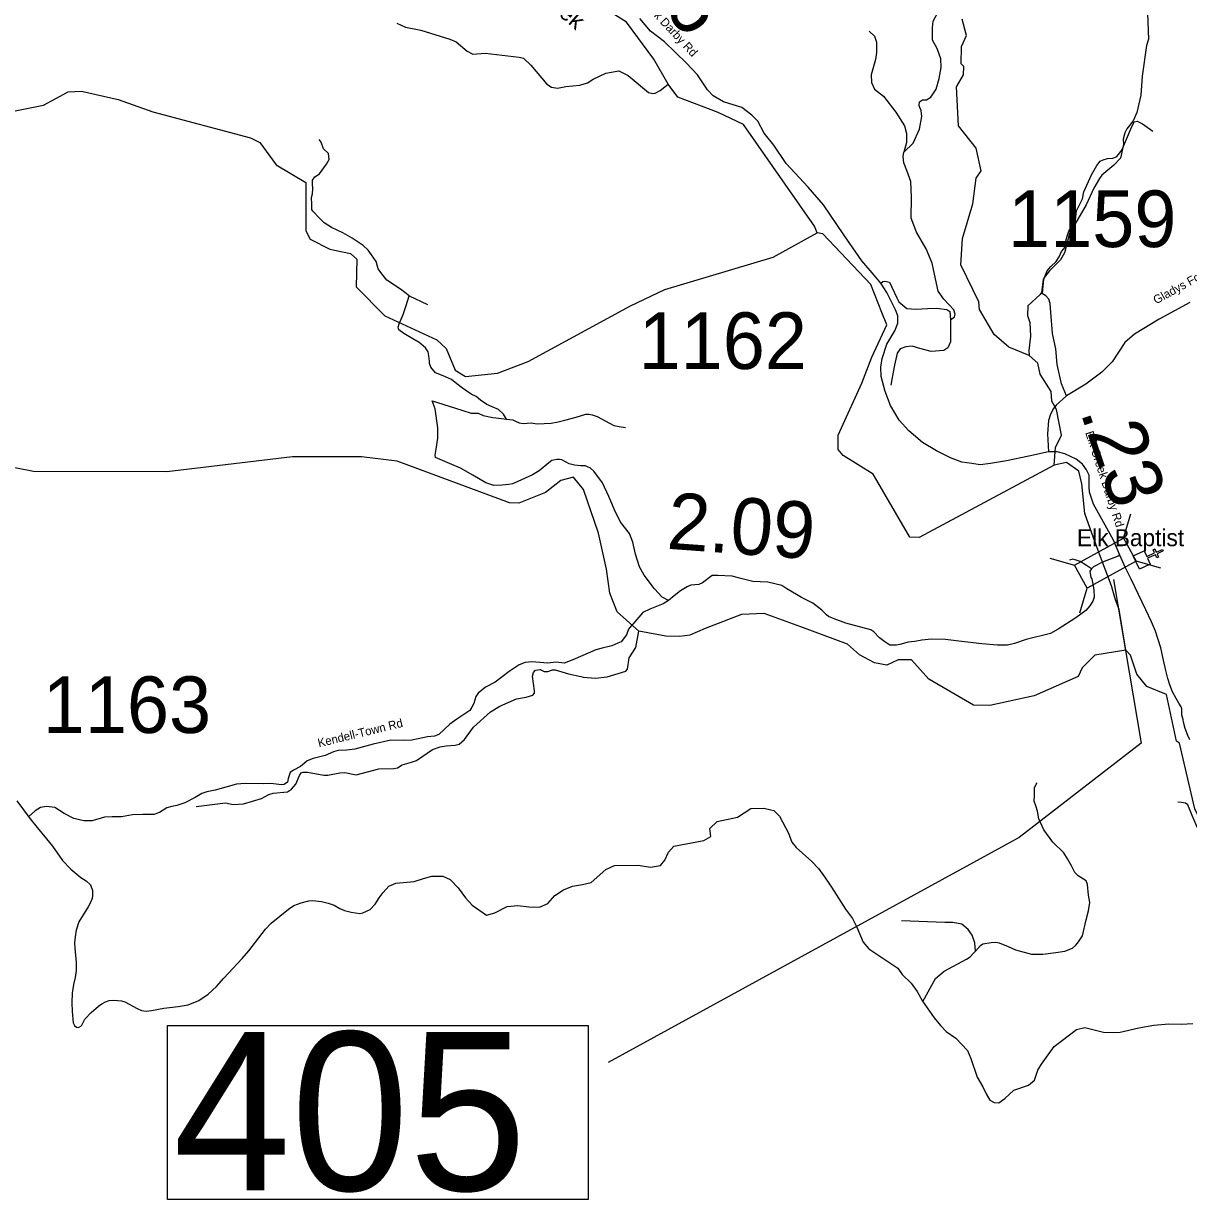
# Model space of a CAD drawing. Extents: x 1248224 to 1454986, y 825081 to 985870.
# Drawn here: x 1277074 to 1287366, y 852532 to 862920 of the extents above; entities that cross this region are included whole.
import ezdxf

# ---------------------------------------------------------------- set-up
doc = ezdxf.new("R2010")
doc.units = 0
for name, color, linetype in [('Exist Boundary Political CountyLine', 7, 'Continuous'), ('Exist Cultural Church CELL', 7, 'Continuous'), ('Exist Cultural Church Label', 7, 'Continuous'), ('Exist Hydrographic Creek Single Shore', 7, 'Continuous'), ('Exist Hydrographic Creek Single Shore Label', 7, 'Continuous'), ('Exist Hydrographic Misc Water Feature', 7, 'Continuous'), ('Exist Road Non-System Type 51', 7, 'Continuous'), ('Exist Road Secondary Mileage Hundredths English Label', 7, 'Continuous'), ('Exist Road Secondary Structure Standard Bridge CELL', 7, 'Continuous'), ('Exist Road Secondary Structure Standard Bridge Number Label', 7, 'Continuous'), ('Exist Road Secondary Type 41 Attributed', 7, 'Continuous'), ('Exist Road Secondary Type 51 Attributed', 7, 'Continuous'), ('Exist Road Secondary Type 51 Label', 7, 'Continuous'), ('Exist Road Secondary Type 51 Number Label', 7, 'Continuous')]:
    doc.layers.add(name, color=color, linetype=linetype)

msp = doc.modelspace()

# ---------------------------------------------------------------- linework, layer by layer
at = {"layer": 'Exist Boundary Political CountyLine'}
for points in [[(1277016, 856053), (1277134, 855896), (1277194, 855817), (1277277, 855718), (1277331, 855652), (1277418, 855527), (1277491, 855449), (1277580, 855377), (1277627, 855347), (1277665, 855312), (1277684, 855262), (1277685, 855217), (1277682, 855191), (1277666, 855155), (1277644, 855117), (1277564, 854986), (1277539, 854912), (1277529, 854853), (1277525, 854798), (1277527, 854753), (1277540, 854626), (1277539, 854556), (1277529, 854493), (1277515, 854430), (1277504, 854355), (1277500, 854268), (1277503, 854194), (1277514, 854093), (1277525, 854069), (1277541, 854054), (1277560, 854052), (1277581, 854063), (1277590, 854073), (1277616, 854124), (1277671, 854183), (1277736, 854240), (1277767, 854262), (1277798, 854279), (1277831, 854289)], [(1277831, 854289), (1277870, 854292), (1277940, 854288), (1277968, 854278), (1278079, 854218), (1278117, 854203), (1278157, 854197), (1278206, 854202), (1278315, 854223), (1278441, 854236), (1278528, 854252), (1278624, 854290), (1278704, 854346), (1278779, 854415), (1278845, 854486), (1279005, 854660), (1279065, 854729), (1279212, 854919), (1279263, 854972), (1279416, 855097), (1279463, 855128), (1279527, 855154), (1279595, 855170), (1279631, 855173), (1279706, 855164), (1279765, 855150), (1279819, 855132), (1279869, 855103), (1279909, 855085), (1279968, 855069), (1280044, 855058), (1280072, 855065), (1280136, 855093), (1280181, 855142), (1280217, 855198), (1280251, 855244), (1280302, 855299), (1280364, 855326), (1280526, 855341), (1280609, 855368), (1280681, 855388), (1280778, 855388), (1280842, 855359), (1280914, 855285), (1280978, 855198), (1281037, 855132), (1281163, 855045), (1281237, 855063), (1281347, 855121), (1281441, 855128), (1281537, 855117), (1281633, 855113), (1281705, 855147), (1281767, 855217), (1281846, 855268), (1281924, 855300), (1282013, 855315), (1282088, 855332), (1282219, 855447), (1282295, 855483), (1282505, 855486), (1282612, 855467), (1282702, 855483), (1282739, 855529), (1282771, 855599), (1282818, 855652), (1283084, 855703), (1283145, 855740), (1283137, 855809), (1283202, 855871), (1283383, 855908), (1283501, 855985), (1283614, 855988), (1283675, 855973), (1283702, 855967), (1283753, 855919), (1283831, 855769), (1283863, 855689), (1283899, 855641), (1284039, 855519), (1284096, 855455), (1284151, 855383), (1284196, 855317), (1284213, 855291), (1284335, 855096), (1284398, 855015), (1284436, 854938), (1284491, 854804), (1284542, 854745), (1284797, 854577), (1284837, 854521), (1284917, 854444), (1284970, 854369), (1285015, 854285), (1285119, 854136), (1285174, 854069), (1285226, 854017), (1285312, 853956), (1285414, 853848), (1285444, 853779), (1285500, 853613)], [(1285500, 853613), (1285550, 853527), (1285580, 853465), (1285612, 853410), (1285648, 853388), (1285691, 853386), (1285743, 853424), (1285823, 853497), (1285953, 853542), (1286005, 853585), (1286035, 853674), (1286067, 853727), (1286180, 853884), (1286378, 854034), (1286449, 854052), (1286615, 854011), (1286700, 854008), (1286762, 854011), (1286928, 854048), (1287059, 854072), (1287191, 854085), (1287303, 854082), (1287404, 854086)]]:
    msp.add_lwpolyline(points, dxfattribs=at)
at = {"layer": 'Exist Cultural Church CELL'}
msp.add_lwpolyline([(1286974, 858262), (1286998, 858211), (1287067, 858243), (1287053, 858272), (1287068, 858279), (1287081, 858250), (1287136, 858275), (1287143, 858261), (1287088, 858235), (1287102, 858206), (1287087, 858199), (1287074, 858228), (1287005, 858196), (1287029, 858144), (1286932, 858099), (1286877, 858217)], close=True, dxfattribs=at)
at = {"layer": 'Exist Hydrographic Creek Single Shore'}
for points in [[(1284086, 861070), (1284062, 861130), (1283435, 862028), (1283211, 862135), (1282856, 862270), (1282770, 862384), (1282642, 862606), (1282401, 862931), (1281748, 863346), (1281569, 863517), (1280995, 864349), (1280777, 864531), (1280688, 864664), (1280667, 864870), (1280635, 865080), (1280391, 865474), (1280334, 865752), (1280154, 866011), (1280001, 866217), (1279969, 866258)], [(1286179, 859019), (1286191, 859176), (1286243, 859284), (1286199, 859511), (1286159, 859584), (1286153, 859670), (1286057, 859823), (1286034, 859921), (1285959, 859986), (1285779, 860061), (1285648, 860172), (1285520, 860395), (1285513, 860460), (1285355, 860789), (1285369, 861021), (1285460, 861328), (1285490, 861554), (1285534, 861619), (1285489, 861820), (1285335, 862017), (1285318, 862359), (1285379, 862466), (1285381, 862541), (1285357, 862565), (1285360, 862716), (1285404, 862813), (1285366, 862958)], [(1276957, 862139), (1277251, 862199), (1277470, 862316), (1277587, 862323), (1277911, 862248), (1278216, 862140), (1279078, 861909), (1279161, 861868), (1279306, 861672), (1279569, 861515), (1279567, 861089), (1279606, 861016), (1279780, 860927), (1279962, 860887), (1280019, 860837), (1280013, 860594), (1280265, 860339), (1280727, 860126), (1280809, 860049), (1280887, 859857), (1280978, 859803), (1281262, 859830), (1281531, 859933), (1282436, 860427), (1282739, 860569), (1283697, 860855), (1284086, 861070)], [(1286179, 859019), (1284987, 858380), (1284904, 858382), (1284580, 858939), (1284315, 859103), (1284271, 859157), (1284271, 859285), (1284479, 859743), (1284568, 859974), (1284701, 860257), (1284657, 860368), (1284560, 860613), (1284136, 861063), (1284086, 861070)], [(1282509, 857552), (1282319, 857723), (1282253, 857889), (1282224, 858099), (1282153, 858417), (1282020, 858804), (1281932, 858914), (1281822, 858883), (1281686, 858778), (1281451, 858684), (1281367, 858686), (1280375, 859053), (1280060, 859093), (1279451, 859092), (1278339, 858960), (1277163, 858964), (1276814, 859030), (1276621, 859303), (1276482, 859430), (1275897, 859705)], [(1286607, 858162), (1286527, 858377), (1286450, 858593), (1286423, 858855), (1286396, 858966), (1286288, 859043), (1286179, 859019)], [(1286685, 857954), (1286607, 858162)], [(1286814, 857385), (1286755, 857744), (1286721, 857828), (1286685, 857954)], [(1286814, 857385), (1286538, 857341), (1286426, 857228), (1286391, 857153), (1286003, 856981), (1285610, 856897), (1285468, 856900), (1285073, 857127), (1284919, 857298), (1284802, 857300), (1284701, 857253), (1284593, 857272), (1284461, 857343), (1284355, 857437), (1283942, 857590), (1283616, 857707), (1283417, 857700), (1283095, 857577), (1282961, 857516), (1282872, 857506), (1282749, 857509), (1282509, 857552)], [(1290064, 852793), (1290015, 852887), (1289863, 853130), (1289742, 853367), (1289499, 853667), (1289302, 854114), (1289141, 854686), (1288925, 855064), (1288789, 855213), (1288652, 855179), (1288449, 855034), (1288244, 854838), (1288177, 854807), (1288102, 854818), (1287963, 854946), (1287810, 855175), (1287422, 855984), (1287286, 856564), (1287261, 856581), (1287171, 856993), (1286998, 857063), (1286909, 857173), (1286855, 857341), (1286814, 857385)]]:
    msp.add_lwpolyline(points, dxfattribs=at)
at = {"layer": 'Exist Hydrographic Misc Water Feature'}
for points in [[(1287005, 863009), (1287014, 862780), (1286996, 862725), (1286956, 862454), (1286944, 862286), (1286910, 862135), (1286876, 862059), (1286822, 861990), (1286805, 861955), (1286790, 861899), (1286793, 861852), (1286766, 861731), (1286708, 861669), (1286600, 861580), (1286579, 861552), (1286529, 861464), (1286463, 861317), (1286315, 861064), (1286271, 860894), (1286234, 860832), (1286137, 860735), (1286092, 860676), (1286083, 860660), (1286068, 860544), (1286056, 860525), (1285947, 860425), (1285945, 860341), (1285964, 860280), (1285971, 860159), (1285956, 860031), (1285959, 859986)], [(1280373, 862922), (1280448, 862887), (1280583, 862860), (1280840, 862780), (1280895, 862757), (1280993, 862674), (1281044, 862649), (1281153, 862658), (1281452, 862623), (1281492, 862614), (1281556, 862552), (1281696, 862385), (1281740, 862358), (1281792, 862348), (1281864, 862362), (1281988, 862376), (1282057, 862395), (1282106, 862427), (1282219, 862480), (1282334, 862503), (1282415, 862461), (1282597, 862311), (1282633, 862302), (1282653, 862305), (1282698, 862328), (1282770, 862384)], [(1278598, 856004), (1278859, 856036), (1278927, 856022), (1279019, 856028), (1279176, 856074), (1279241, 856109), (1279281, 856120), (1279406, 856133), (1279442, 856157), (1279479, 856201), (1279511, 856276), (1279528, 856300), (1279544, 856307), (1279584, 856306), (1279728, 856280), (1279764, 856280), (1279868, 856301), (1279912, 856304), (1280012, 856284), (1280213, 856335), (1280345, 856338), (1280377, 856345), (1280418, 856372), (1280503, 856394), (1280547, 856411), (1280686, 856507), (1280754, 856530), (1280807, 856540), (1280887, 856544), (1280923, 856555), (1280970, 856595), (1281049, 856705), (1281200, 856839), (1281283, 856889), (1281429, 856955), (1281514, 856969), (1281574, 856988), (1281587, 857004), (1281587, 857024), (1281572, 857156), (1281581, 857188), (1281597, 857207), (1281638, 857215), (1281673, 857196), (1281705, 857195), (1281746, 857210), (1281770, 857210), (1281889, 857174), (1281998, 857153), (1282018, 857145), (1282126, 857138), (1282230, 857150), (1282394, 857198), (1282410, 857217), (1282425, 857317), (1282483, 857408), (1282509, 857552)]]:
    msp.add_lwpolyline(points, dxfattribs=at)
at = {"layer": 'Exist Road Non-System Type 51'}
for points in [[(1284852, 861784), (1284935, 861864), (1284989, 861986), (1285011, 862097), (1285005, 862152), (1284992, 862177), (1284986, 862196), (1284989, 862228), (1285015, 862247), (1285053, 862247), (1285091, 862270), (1285136, 862340), (1285164, 862434), (1285180, 862530), (1285177, 862607), (1285145, 862699), (1285104, 862773), (1285104, 862881), (1285110, 862939), (1285199, 863105)], [(1284546, 862852), (1284593, 862807), (1284609, 862756), (1284609, 862664), (1284600, 862603), (1284562, 862466), (1284565, 862399), (1284593, 862341), (1284673, 862278), (1284782, 862137), (1284858, 862016), (1284874, 861949), (1284874, 861869), (1284852, 861784)], [(1286289, 859630), (1286244, 859738), (1286206, 859909), (1286193, 860045), (1286166, 860183), (1286149, 860370), (1286144, 860447), (1286132, 860485), (1286106, 860513), (1286077, 860531), (1286079, 860570), (1286087, 860663), (1286119, 860734), (1286151, 860772), (1286198, 860817), (1286224, 860859), (1286245, 860906), (1286266, 860929), (1286281, 860953), (1286283, 860997), (1286294, 861040), (1286309, 861085), (1286368, 861183), (1286376, 861266), (1286431, 861370), (1286442, 861432), (1286508, 861583), (1286555, 861666), (1286587, 861704), (1286612, 861717), (1286650, 861726), (1286699, 861730), (1286729, 861743), (1286748, 861762), (1286778, 861800), (1286861, 861996), (1286886, 862050), (1286912, 862056), (1286961, 862033), (1287050, 861969)], [(1280481, 860513), (1280404, 860574), (1280284, 860653), (1280241, 860709), (1280208, 860752), (1280190, 860817), (1280149, 860875), (1280118, 860919), (1280074, 860960), (1279977, 861025), (1279895, 861071), (1279796, 861117), (1279730, 861158), (1279691, 861198), (1279629, 861262), (1279621, 861277), (1279621, 861324), (1279619, 861382), (1279627, 861416), (1279629, 861459), (1279626, 861503), (1279626, 861536), (1279649, 861566), (1279690, 861592), (1279751, 861678), (1279774, 861720), (1279769, 861771), (1279724, 861814), (1279705, 861873), (1279685, 861895)], [(1285263, 860302), (1285299, 860328), (1285305, 860353), (1285292, 860391), (1285206, 860484), (1285155, 860557), (1285123, 860707), (1285101, 860803), (1285050, 860928), (1284964, 861078), (1284916, 861199), (1284919, 861385), (1284913, 861523), (1284877, 861622), (1284852, 861689), (1284846, 861746), (1284852, 861784)], [(1284647, 860626), (1284667, 860640), (1284683, 860644), (1284724, 860634), (1284744, 860592), (1284788, 860497), (1284807, 860462), (1284878, 860401), (1284960, 860398), (1285059, 860401), (1285139, 860404), (1285232, 860395), (1285257, 860375), (1285263, 860302)], [(1281342, 859426), (1281315, 859470), (1281270, 859510), (1281214, 859534), (1281168, 859554), (1281111, 859592), (1281073, 859626), (1281029, 859646), (1280991, 859671), (1280953, 859699), (1280902, 859738), (1280855, 859776), (1280782, 859807), (1280715, 859835), (1280673, 859885), (1280660, 859918), (1280661, 859938), (1280656, 859984), (1280648, 860020), (1280625, 860054), (1280569, 860102), (1280515, 860135), (1280435, 860183), (1280390, 860214), (1280384, 860237), (1280394, 860268), (1280427, 860350), (1280456, 860429), (1280481, 860513)], [(1280481, 860513), (1280642, 860439)], [(1285263, 860302), (1285263, 860184), (1285263, 860107), (1285241, 860056), (1285206, 860031), (1285094, 860024), (1284992, 860050), (1284925, 860069), (1284868, 860063), (1284820, 860047), (1284791, 860008), (1284769, 859903), (1284747, 859794), (1284737, 859724)], [(1282773, 857823), (1282717, 857853), (1282650, 857927), (1282557, 858048), (1282515, 858120), (1282480, 858231), (1282456, 858337), (1282429, 858415), (1282350, 858512), (1282303, 858603), (1282244, 858741), (1282190, 858864), (1282113, 858965), (1282084, 858993), (1282056, 859004), (1282035, 859013), (1281994, 859013), (1281941, 859019), (1281895, 859031), (1281830, 859067), (1281808, 859070), (1281785, 859070), (1281743, 859059), (1281715, 859039), (1281631, 858970), (1281572, 858934), (1281442, 858875), (1281394, 858855), (1281363, 858848), (1281304, 858843), (1281230, 858840), (1281158, 858863), (1281044, 858930), (1280935, 858993), (1280837, 859034), (1280714, 859086), (1280711, 859106), (1280721, 859160), (1280734, 859257), (1280734, 859347), (1280712, 859517), (1280684, 859587)], [(1280684, 859587), (1280883, 859526), (1281028, 859479), (1281090, 859477), (1281134, 859457), (1281220, 859441), (1281298, 859431), (1281342, 859426)], [(1281342, 859426), (1281398, 859418), (1281421, 859408), (1281454, 859393), (1281489, 859387), (1281559, 859392), (1281613, 859385), (1281674, 859387), (1281736, 859390), (1281797, 859402), (1281856, 859415), (1281956, 859443), (1282043, 859469), (1282067, 859470), (1282097, 859462), (1282141, 859447), (1282212, 859410), (1282288, 859369), (1282335, 859360), (1282393, 859350)], [(1286509, 858102), (1286465, 858133), (1286410, 858167), (1286366, 858182), (1286344, 858187), (1286314, 858179)], [(1285483, 854725), (1285528, 854775), (1285550, 854790), (1285623, 854803), (1285665, 854805), (1285695, 854800), (1285773, 854768), (1285838, 854738), (1285980, 854700), (1286080, 854698), (1286193, 854713), (1286273, 854725), (1286340, 854753), (1286370, 854778), (1286395, 854808), (1286430, 854860), (1286463, 855003), (1286483, 855081), (1286495, 855156), (1286482, 855220), (1286475, 855315), (1286462, 855347), (1286392, 855390), (1286362, 855422), (1286332, 855480), (1286297, 855542), (1286265, 855593), (1286167, 855690), (1286087, 855798), (1286045, 855894), (1286032, 855962), (1286017, 856009), (1286002, 856052), (1286005, 856102), (1286005, 856169), (1286020, 856202), (1286030, 856212)], [(1287708, 855339), (1287668, 855364), (1287591, 855472), (1287566, 855527), (1287501, 855667), (1287496, 855697), (1287481, 855745), (1287466, 855777), (1287443, 855820), (1287398, 855925), (1287361, 856018), (1287341, 856033), (1287303, 856040), (1287273, 856043)], [(1285483, 854725), (1285480, 854800), (1285455, 854868), (1285420, 854918), (1285363, 854963), (1285283, 854980), (1285213, 854978), (1284830, 854993)], [(1285019, 854280), (1285130, 854483), (1285208, 854548), (1285405, 854655), (1285438, 854675), (1285468, 854708), (1285483, 854725)]]:
    msp.add_lwpolyline(points, dxfattribs=at)
at = {"layer": 'Exist Road Secondary Structure Standard Bridge CELL'}
for p, q in [((1286793, 858373), (1286856, 858590)), ((1286141, 858198), (1286358, 858135)), ((1286902, 858175), (1287120, 858112)), ((1286407, 857715), (1286470, 857932))]:
    msp.add_line(p, q, dxfattribs=at)
msp.add_lwpolyline([(1286358, 858135), (1286793, 858374), (1286904, 858171), (1286470, 857932)], close=True, dxfattribs=at)
at = {"layer": 'Exist Road Secondary Structure Standard Bridge Number Label'}
msp.add_lwpolyline([(1286704, 858010), (1286949, 856563), (1285870, 855729), (1282239, 853742)], dxfattribs=at)
msp.add_lwpolyline([(1278346, 854069), (1282062, 854069), (1282062, 852532), (1278346, 852532)], close=True, dxfattribs=at)
at = {"layer": 'Exist Road Secondary Type 41 Attributed'}
for points in [[(1284047, 857801), (1283947, 857849), (1283903, 857876), (1283819, 857927), (1283774, 857955), (1283650, 857986), (1283581, 857988), (1283516, 857992), (1283424, 858016), (1283335, 858037), (1283207, 858045), (1283159, 858043), (1283073, 857980), (1283039, 857966), (1282970, 857959), (1282937, 857943), (1282878, 857909), (1282821, 857864), (1282773, 857823), (1282724, 857795), (1282608, 857748), (1282545, 857717), (1282456, 857615), (1282442, 857598)], [(1282442, 857598), (1282420, 857570), (1282402, 857519), (1282355, 857458), (1282326, 857446), (1282272, 857422), (1282186, 857401), (1282131, 857387), (1282014, 857338), (1281928, 857298), (1281851, 857271), (1281780, 857279), (1281705, 857271), (1281565, 857281), (1281506, 857277), (1281452, 857256), (1281364, 857195), (1281242, 857102), (1281155, 857057), (1281090, 857006), (1281070, 856975), (1281053, 856912), (1281035, 856882), (1281017, 856851), (1280903, 856774), (1280841, 856732), (1280743, 856641), (1280705, 856624), (1280644, 856620), (1280560, 856600), (1280504, 856590), (1280441, 856588), (1280319, 856590), (1280164, 856555), (1280000, 856511), (1279929, 856502), (1279855, 856498), (1279813, 856486), (1279740, 856454), (1279691, 856443), (1279632, 856427), (1279581, 856407), (1279557, 856385), (1279520, 856356), (1279459, 856324), (1279431, 856305), (1279412, 856252), (1279406, 856218), (1279378, 856197), (1279353, 856194), (1279258, 856208), (1279195, 856204), (1279032, 856208), (1278955, 856202), (1278862, 856174), (1278766, 856147), (1278695, 856133), (1278648, 856119), (1278591, 856084), (1278498, 856035), (1278430, 856013), (1278385, 856003), (1278339, 855991), (1278274, 855952), (1278225, 855934), (1278127, 855934), (1278038, 855930), (1277940, 855911), (1277857, 855911), (1277790, 855909), (1277680, 855877), (1277607, 855877), (1277520, 855897), (1277432, 855942), (1277351, 855995), (1277278, 856003), (1277223, 855995), (1277178, 855966), (1277120, 855915)]]:
    msp.add_lwpolyline(points, dxfattribs=at)
at = {"layer": 'Exist Road Secondary Type 51 Attributed'}
for points in [[(1286130, 859137), (1285956, 859098), (1285758, 859057), (1285617, 859032), (1285527, 859021), (1285452, 859032), (1285364, 859046), (1285263, 859083), (1285139, 859145), (1285016, 859219), (1284895, 859321), (1284811, 859415), (1284733, 859546), (1284687, 859669), (1284651, 859801), (1284647, 859883), (1284660, 859962), (1284702, 860086), (1284773, 860206), (1284797, 860274), (1284797, 860338), (1284777, 860391), (1284702, 860545), (1284647, 860626), (1284588, 860697), (1284480, 860822), (1284322, 861052), (1284142, 861317), (1284005, 861475), (1283812, 861682), (1283702, 861846), (1283616, 861952), (1283561, 862058), (1283509, 862109), (1283420, 862177), (1283259, 862229), (1283166, 862280), (1283116, 862335), (1283027, 862465), (1282930, 862568), (1282834, 862663), (1282736, 862757), (1282613, 862852), (1282518, 862963)], [(1287378, 860456), (1287106, 860309), (1286888, 860177), (1286803, 860101), (1286693, 859930), (1286600, 859839), (1286458, 859735), (1286289, 859630), (1286197, 859549), (1286174, 859518), (1286146, 859468), (1286128, 859414), (1286121, 859294), (1286130, 859137)], [(1286761, 858224), (1286705, 858357), (1286527, 858675), (1286492, 858779), (1286490, 858824), (1286489, 858930), (1286465, 858978), (1286431, 859028), (1286374, 859072), (1286274, 859120), (1286205, 859137), (1286130, 859137)], [(1286761, 858224), (1286746, 858216), (1286607, 858162)], [(1287379, 856592), (1287361, 856632), (1287338, 856693), (1287322, 856750), (1287318, 856773), (1287307, 856811), (1287308, 856846), (1287306, 856866), (1287301, 856884), (1287281, 856916), (1287256, 856959), (1287225, 857015), (1287201, 857078), (1287184, 857134), (1287165, 857205), (1287145, 857295), (1287121, 857404), (1287097, 857480), (1287074, 857551), (1287038, 857635), (1286990, 857742), (1286861, 858011), (1286807, 858118), (1286761, 858224)], [(1286607, 858162), (1286527, 858122), (1286509, 858102), (1286494, 858083), (1286502, 858027), (1286511, 858015), (1286529, 857917), (1286533, 857854), (1286521, 857818), (1286495, 857775), (1286460, 857736), (1286371, 857669), (1286216, 857570), (1286147, 857531), (1285933, 857478), (1285829, 857444), (1285768, 857428), (1285679, 857428), (1285541, 857440), (1285338, 857464), (1285219, 857480), (1285097, 857482), (1285009, 857472), (1284948, 857462), (1284889, 857456), (1284816, 857434), (1284786, 857430), (1284727, 857430), (1284682, 857458), (1284635, 857493), (1284585, 857545), (1284561, 857563), (1284459, 857591), (1284339, 857624), (1284236, 857662), (1284187, 857683), (1284169, 857697), (1284128, 857738), (1284047, 857801)]]:
    msp.add_lwpolyline(points, dxfattribs=at)

# ---------------------------------------------------------------- texts
at = {"layer": 'Exist Cultural Church Label'}
msp.add_text('Elk Baptist', height=150, dxfattribs=at).set_placement((1286380, 858303))
at = {"layer": 'Exist Hydrographic Creek Single Shore Label'}
msp.add_text('Creek', height=150, rotation=318.9814, dxfattribs=at).set_placement((1281550, 863209))
at = {"layer": 'Exist Road Secondary Mileage Hundredths English Label'}
for s, rotation, p in [('1.96', 304.5901, (1282190, 863842)), ('.23', 288.6628, (1286408, 859490)), ('2.09', 355.852, (1282750, 858281))]:
    msp.add_text(s, height=500, rotation=rotation, dxfattribs=at).set_placement(p)
at = {"layer": 'Exist Road Secondary Structure Standard Bridge Number Label'}
msp.add_text('405', height=1400, dxfattribs=at).set_placement((1278396, 852612))
at = {"layer": 'Exist Road Secondary Type 51 Label'}
for s, rotation, p in [('Elk Creek Darby Rd', 313.064, (1282377, 863267)), ('Gladys Fork Rd', 28.8197, (1287080, 860438)), ('Elk Creek Darby Rd', 288.0227, (1286453, 859306)), ('Kendell-Town Rd', 13.7154, (1279684, 856526))]:
    msp.add_text(s, height=75, rotation=rotation, dxfattribs=at).set_placement(p)
at = {"layer": 'Exist Road Secondary Type 51 Number Label'}
for s, p in [('1159', (1285772, 860945)), ('1162', (1282508, 859868)), ('1163', (1277244, 856653))]:
    msp.add_text(s, height=500, dxfattribs=at).set_placement(p)

doc.saveas('drawing.dxf')
